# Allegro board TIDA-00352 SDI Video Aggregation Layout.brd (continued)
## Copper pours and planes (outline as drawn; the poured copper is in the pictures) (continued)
VDDRB_HS on L8_PWR: 77.6,177.16 77.6,116.08 37.08,116.08 37.08,74.93 42.55,74.93 42.55,79.25 48.01,79.25 48.01,108.2 86.23,108.2 86.23,177.16
VDDRB_LS on TOP (solid shape): 85.09,137.54 83.31,137.54 83.31,139.45 85.09,139.45
VDDRB_LS on L8_PWR: 86.87,160.02 86.87,107.57 48.51,107.57 48.51,74.68 64.64,74.68 64.64,97.54 94.36,97.54 94.36,160.02
VDDT on TOP (solid shape): 114.3,127 112.39,127 112.39,128.78 114.3,128.78
VDDT on L5_PWR: 29.97,50.17 29.97,73.32 30.03,73.41 30.14,73.39 30.88,73.7 30.14,74.01 30.03,73.99 29.97,74.08 29.97,91.8 30.46,92.67 29.97,93.54 29.97,94.59 30.01,94.6 30.45,95.2 30.01,95.81 29.97,95.82 29.97,96.52 108.46,96.52 108.46,99.34 108.49,99.41 108.56,99.44 109.02,99.87 108.56,100.3 108.49,100.33 108.46,100.41 108.46,106.4 108.49,106.47 108.56,106.5 109.02,106.93 108.56,107.37 108.49,107.39 108.46,107.47 108.46,117.43 108.47,117.6 108.46,117.77 108.46,117.78 108.46,129.41 118.14,129.41 118.49,129.23 118.84,129.41 126.36,129.41 126.36,88.65 99.44,88.65 99.44,81.41 99.31,81.41 99.31,71.5 47.75,71.5 47.75,76.33 42.93,76.33 42.93,73.79 43.43,73.79 43.43,72.64 42.93,72.64 42.93,50.17
1P0V_A1 on TOP (solid shape): 91.82,43.56 91.82,40.64 92.68,40.64 92.68,38.88 92.32,38.88 92.32,39.87 92.03,39.87 92.03,38.88 91.67,38.88 91.67,39.87 91.38,39.87 91.38,38.88 91.02,38.88 91.02,39.87 90.11,39.87 90.11,37.61 89.1,37.61 89.09,43.56
1P0V_A2 on TOP (solid shape): 111.63,124.71 111.63,121.79 112.49,121.79 112.49,120.03 112.14,120.03 112.14,121.02 111.84,121.02 111.84,120.03 111.49,120.03 111.49,121.02 111.19,121.02 111.19,120.03 110.84,120.03 110.84,121.02 109.93,121.02 109.93,118.76 108.91,118.76 108.9,124.72
1P0V_D1 on TOP (solid shape): 114.3,87.38 114.3,84.45 115.16,84.45 115.16,82.69 114.8,82.69 114.8,83.68 114.51,83.68 114.51,82.69 114.15,82.69 114.15,83.68 113.86,83.68 113.86,82.69 113.5,82.69 113.5,83.68 112.59,83.68 112.59,81.42 111.58,81.42 111.57,87.38
1P0V_D2 on TOP (solid shape): 112.27,43.81 112.27,40.89 113.13,40.89 113.13,39.13 112.77,39.13 112.77,40.12 112.48,40.12 112.48,39.13 112.12,39.13 112.12,40.12 111.83,40.12 111.83,39.13 111.47,39.13 111.47,40.12 110.56,40.12 110.56,37.86 109.55,37.86 109.54,43.82
1P5V on TOP (solid shape): 93.34,150.37 90.42,150.37 90.42,149.51 88.66,149.51 88.66,149.87 89.65,149.87 89.65,150.16 88.66,150.16 88.66,150.52 89.65,150.52 89.65,150.81 88.66,150.81 88.66,151.17 89.65,151.17 89.65,152.07 87.39,152.07 87.39,153.09 93.35,153.1
1P8V on TOP (solid shape): 74.29,150.37 71.37,150.37 71.37,149.51 69.61,149.51 69.61,149.87 70.6,149.87 70.6,150.16 69.61,150.16 69.61,150.52 70.6,150.52 70.6,150.81 69.61,150.81 69.61,151.17 70.6,151.17 70.6,152.07 68.34,152.07 68.34,153.09 74.3,153.1
3P3V on TOP (solid shape): 98.42,124.71 98.42,121.79 99.29,121.79 99.28,120.03 98.93,120.03 98.93,121.02 98.63,121.02 98.63,120.03 98.28,120.03 98.28,121.02 97.98,121.02 97.98,120.03 97.63,120.03 97.63,121.02 96.72,121.02 96.72,118.76 95.7,118.76 95.69,124.72
3P3V on BOTTOM (solid shape): 55.12,37.34 53.85,37.34 53.85,39.12 50.67,39.12 50.67,40.51 53.85,40.51 53.85,43.05 55.12,43.05
3P3V on L5_PWR: 0.64,0.64 0.64,177.16 14.22,177.16 14.22,137.16 55.24,137.16 55.24,129.41 107.82,129.41 107.82,97.16 29.34,97.16 29.34,49.4 126.36,49.4 126.36,0.64 ; 2 cut-outs
3P3V_CLK on TOP (solid shape): 57.28,171.7 55.88,171.7 55.88,174.12 57.28,174.12
3P3V_CLK on TOP (solid shape): 57.28,165.1 55.88,165.1 55.88,167.51 57.28,167.51
3P3V_CLK on TOP (solid shape): 57.28,137.29 55.88,137.29 55.88,139.7 57.28,139.7
3P3V_CLK on TOP (solid shape): 57.4,158.5 56.01,158.5 56.01,160.91 57.4,160.91
3P3V_CLK on TOP (solid shape): 57.4,151.64 56.01,151.64 56.01,154.05 57.4,154.05
3P3V_CLK on TOP (solid shape): 57.4,144.15 56.01,144.15 56.01,146.56 57.4,146.56
3P3V_CLK on TOP (solid shape): 57.66,130.18 56.26,130.18 56.26,132.59 57.66,132.59
3P3V_CLK on TOP (solid shape): 64.26,172.97 64.26,170.05 65.12,170.05 65.12,168.29 64.76,168.29 64.76,169.28 64.47,169.28 64.47,168.29 64.11,168.29 64.11,169.28 63.82,169.28 63.82,168.29 63.46,168.29 63.46,169.28 62.56,169.28 62.56,167.02 61.54,167.02 61.53,172.98
3P3V_CLK on BOTTOM (solid shape): 57.4,171.7 55.88,171.7 55.88,174.12 57.4,174.12
3P3V_CLK on BOTTOM (solid shape): 57.4,165.1 55.88,165.1 55.88,167.51 57.4,167.51
3P3V_CLK on BOTTOM (solid shape): 57.4,158.5 55.88,158.5 55.88,160.91 57.4,160.91
3P3V_CLK on BOTTOM (solid shape): 57.4,151.64 55.88,151.64 55.88,154.05 57.4,154.05
3P3V_CLK on BOTTOM (solid shape): 57.4,137.16 55.88,137.16 55.88,139.57 57.4,139.57
3P3V_CLK on BOTTOM (solid shape): 57.53,144.15 56.01,144.15 56.01,146.56 57.53,146.56
3P3V_CLK on BOTTOM (solid shape): 57.78,130.18 56.26,130.18 56.26,132.59 57.78,132.59
3P3V_CLK on L5_PWR: 55.75,177.16 55.75,129.92 126.36,129.92 126.36,177.16
3P3V_CLK on L12_PWR: 28.96,104.52 28.96,114.3 56.01,114.3 56.01,133.22 55.88,133.22 55.88,177.29 126.36,177.16 126.36,104.52
3P3V_RX on BOTTOM (solid shape): 59.69,38.23 59.44,38.23 59.44,36.96 58.93,36.96 58.93,37.34 56.9,37.34 56.9,40.01 59.69,40.01
3P3V_RX on L8_PWR: 48.77,0.64 48.77,21.72 36.07,21.72 36.07,34.29 41.53,34.29 41.53,26.8 46.23,26.8 46.23,34.29 53.98,34.29 53.98,40.01 61.72,40.01 61.72,43.69 126.36,43.69 126.36,0.64
3P3V_TX on BOTTOM (solid shape): 59.44,42.29 59.69,42.29 59.69,40.51 56.9,40.51 56.9,43.18 58.93,43.18 58.93,43.31 59.44,43.31
3P3V_TX on L8_PWR: 0.64,0.64 0.64,43.69 60.96,43.69 60.96,40.51 53.34,40.51 53.34,34.92 45.72,34.92 45.72,27.3 41.91,27.3 41.91,35.05 38.61,35.05 38.61,34.42 35.56,34.42 35.56,21.21 48.26,21.21 48.26,0.64
CLK_DVDD on BOTTOM (solid shape): 55.5,130.18 54.1,130.18 54.1,132.59 55.5,132.59
CLK_DVDD on L12_PWR: 55.5,132.59 42.42,132.59 42.42,122.05 11.43,122.05 11.43,146.3 19.3,146.3 19.3,177.16 0.64,177.16 0.64,104.52 28.45,104.52 28.45,114.94 55.5,114.94
CLK_VCC on BOTTOM (solid shape): 55.24,144.15 53.85,144.15 53.85,146.56 55.24,146.56
CLK_VCC on L12_PWR: 55.37,140.97 32.64,140.97 32.64,130.05 19.81,130.05 19.81,177.16 55.37,177.16
CLK_VDD_IN on BOTTOM (solid shape): 55.12,137.16 53.72,137.16 53.72,139.57 55.12,139.57
CLK_VDD_IN on L12_PWR: 55.37,140.34 33.27,140.34 33.27,129.41 19.3,129.41 19.3,145.8 12.06,145.8 12.06,122.68 41.78,122.68 41.78,133.22 55.37,133.22
CLK_VDD_OUTA on BOTTOM (solid shape): 55.12,151.64 53.72,151.64 53.72,154.05 55.12,154.05
CLK_VDD_OUTA on L5_PWR: 55.24,155.07 31.88,155.07 31.88,142.37 20.07,142.37 20.07,137.67 55.24,137.67
CLK_VDD_OUTB on BOTTOM (solid shape): 55.12,158.5 53.72,158.5 53.72,160.91 55.12,160.91
CLK_VDD_OUTB on L5_PWR: 55.24,164.08 27.05,164.08 27.05,146.3 14.86,146.3 14.86,137.67 19.43,137.67 19.43,142.88 31.24,142.88 31.24,155.7 55.24,155.7
CLK_VDD_PLL on BOTTOM (solid shape): 55.12,165.1 53.72,165.1 53.72,167.51 55.12,167.51
CLK_VDD_PLL on L5_PWR: 55.24,170.43 22.23,170.43 22.23,146.81 26.54,146.81 26.54,164.72 55.24,164.72
CLK_VDD_PLL_A on BOTTOM (solid shape): 55.12,171.7 53.72,171.7 53.72,174.12 55.12,174.12
CLK_VDD_PLL_A on L5_PWR: 55.24,171.07 21.59,171.07 21.59,146.81 14.86,146.81 14.86,177.16 55.24,177.16
Net_257 on TOP (solid shape): 100.25,149.44 100.42,149.32 100.54,149.14 100.58,148.94 100.52,148.7 100.42,148.54 100.23,148.41 100.03,148.38 99.81,148.42 99.64,148.53 99.51,148.72 99.47,148.93 99.51,149.16 99.62,149.31 99.82,149.45 100.03,149.48
Net_258 on TOP (solid shape): 97.92,151.04 97.92,149.15 98.06,148.46 98.28,148.14 98.64,147.98 99.22,148 99.08,146.99 98.56,146.99 98.43,146.14 98.95,146.14 98.69,144.27 98.69,144.11 98.77,143.93 98.96,143.69 99.1,143.59 99.33,143.49 99.61,143.41 100.04,143.37 100.39,143.41 100.54,143.48 100.57,143.55 100.58,144.07 100.41,144.09 100.21,144.13 100.14,144.19 100.1,144.31 100.37,146.14 100.91,146.14 101.06,146.98 100.53,147 100.71,148.07 100.94,148.15 101.6,148.2 102.3,148.08 102.66,147.84 103.23,147.74 103.21,146.56 103.38,146.14 103.51,145.56 103.58,144.64 103.51,143.58 103.42,143.27 103.28,143.11 103,142.99 102.21,142.79 101.63,142.51 100.48,142.07 99.77,141.52 99.23,140.88 98.99,140.1 99.03,139.56 99.12,139.15 99.31,138.56 99.31,138.39 98.88,138.49 98.41,138.54 98,138.84 97.8,138.91 97.59,139.27 96.81,140.89 96.49,141.52 96.03,142.63 95.68,143.12 95.43,143.26 95.07,143.25 94.64,143.01 94.49,142.88 94.18,142.81 93.96,142.87 93.69,143.17 93.28,143.65 92.95,144.18 92.56,144.64 92.15,145.06 91.66,145.25 91.47,145.42 91.4,145.6 91.29,145.78 95.07,145.78 95.07,151.05
Net_259 on TOP (solid shape): 99.92,144.56 98.95,144.55 99.43,147.85 100.4,147.86

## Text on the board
BOTTOM: LAYER16-BOTTOM(TESTER)SIDE
Package Geometry/Pastemask Bottom: SPB
Ref Des/Silkscreen Bottom: SBW
User.Comments: MB | MT
TOP: TLK10xxxEVM | MOTHER BOARD | 6566789 | REV B | J | N | LAYER1-TOP-DUT SIDE
Board Geometry/Soldermask Top: TLK10xxxEVM | MOTHER BOARD | 6566789 | REV B | J | N
Package Geometry/Pastemask Top: SPT
Ref Des/Silkscreen Top: HIGH | LOW | 2p5V | MDIOV | GND | 3P3V_CLK | ST/GPI1 | SIGNAL* | RCLK_SEL | MODE_SEL | PDTRXB | GPI1 | ST | TESTEN | 232 | H10 | M9 | MDIO_B2B_RLY | MDIO_CON_RLY | PRBSEN | 022 | 081 | REF_SEL | SI_MODE0 | SI_MODE1 | 3P3V | 1P8V | 1P5V | PDTRXA | 1P0V_D2 | 1P0V_D1 | M9 * | 1P0V_A2 | H10 * | MODE/REFCLK_SEL | 1P0V_A1 | GPIO | B2B_RLY | CON_RLY | I2C_ADDR | I2C_GPIO_ADDR | STATUS1/PIN0 | SPI_LE2 | SPI_CLK/PIN4 | SPI_LE1/PIN3 | SPI_MISO/PIN2 | SPI_MOSI/PIN1 | DIS | EN | PRI_REF | SEC_REF | (30.72MHZ) | (31.25MHZ) | CLK BUFFER INPUT | CLKA | (STATUS0) | CLKB | PLL_LOCK | RST/PWR | 3p3V | SYNCN | PDN | RST | BTN | PRI_REF_IN_N | STATUS1 | PRI_OSC | SEC_OSC | CLK | EXT | GEN | SMA | RESET | MDC | OUTPUT | MDIO | INPUT | I2C | JTAG | MOD_DEF2_SDA | MOD_DEF1_SCL | MOD DETECT | SFP+ | TX_DIS | JTAG_V | PRTAD0 | 12C_LS_EN | REGULATOR | DISABLE | 23 | 22 | 1p0V_D1 | 5V | REG | PRI_REF_IN_P | INT2 | RESET2 | INT1 | RESET1 | SDA | SCL | TX_FAULT | TX DIS | TCK | TMS | RX_LOS | TDI | TDO | TRST | LS_OK | OUT_B | PRTAD4 | PRTAD3 | OUT_A | PRTAD2 | PRTAD1 | PRBS | PASS | LOSB | IN | OUT | LOSA | LS_OKINB | LS_OKINA | AMUXB | AMUXA | HSTXBn | HSTXBp | HSRXBp | HSRXBn | USB DONGLE | CLKOUTBn | REFCLK0n | CLKOUTBp | REF | CLK0p | RST/ | PWR | CLKOUTAn | CLK1n | REFCLK1p | CLKOUTAp | 1p8V | 3p3V_CLK | 1p5V | VOLTAGE MONITOR DONGLE | 1p5/8V | MAIN | STW | PLUG | 1p0V_A1 | BJ | 1p0V_D2 | 1p0V_A2 | +5V
L2_GND: LAYER2-GND
L3_SIG2: LAYER3-SIGNAL
L4_GND: LAYER4-GND
L5_PWR: LAYER5-PWR
L6_GND: LAYER6-GND
L7_GND: LAYER7-GND
L8_PWR: LAYER8-PWR
L9_GND: LAYER9-GND
L10_PWR: LAYER10-PWR
L11_GND: LAYER11-GND
L12_PWR: LAYER12-PWR
L13_GND: LAYER13-GND
L14_SIG3: LAYER14-SIGNAL
L15_GND: LAYER15-GND
PAGE_OUTLINE: J. NERGER | LT/DFW TEST | 04/16/13 | 6566789 | A | TLK10xxx EVM MOTHER BOARD | Texas Instruments Inc. | 12500 TI Boulevard | Dallas, TX 75243 | WO# 73776
COMPVAL_TYPE_TOP: FR-4 | Pre-preg 0.010" | Core 0.005" | 1.0oz / 1.0oz Layer 8 & 9 | (material) | LAYER 8 | LAYER 9
COMPVAL_TYPE_BOTTOM: ASSEMBLY | 1 | / | 2
USER_PART_NUM_TOP: ASSEMBLY | 2 | /
User.8: FABRICATION | 1 | / | GENERAL NOTES. UNLESS OTHERWISE SPECIFIED | 1.  ALL FABRICATION ITEMS MUST MEET OR EXCEED BEST | INDUSTRY PRACTICE : IPC-A-600C (Commercial std.) | 2.  LAMINATE MATERIAL  :  ROGERS 4350B or EQUIVALENT BETWEEN | LAYERS 1 & 2 AND LAYERS 15 &16 | FR4 POLYCLAD OR EQUIVALENT FOR ALL OTHER LAYERS | 3.  COPPER WEIGHT  : 1oz START INTERNAL, 1/2oz START EXTERNAL | 4.  FINISHED BOARD THICKNESS :  .111 +/-10% | 5.  MAXIMUM WARP AND TWIST TO BE :  .005 INCH PER INCH | 6.  MINIMUM COPPER WALL THICKNESS OF PLATED-THRU | HOLES TO BE .001 INCH. THERE MUST BE 1MIL OR GREATER PLATING ON | EACH SIDE OF THE BARREL WHEN VIEWED IN THE CROSS SECTION | 7.  MINIMUM ANNULAR RING OF PLATED-THRU HOLES | TO BE .002 INCH | 8.  MINIMUM ALLOWABLE LINE REDUCTION TO BE | 20% OR .002 WHICHEVER IS GREATER | 9.  0.010 SIGNAL LINES ON LAYERS 1 & 16 TO BE | IMPEDANCE CONTROLLED 50 OHMS +/- 10% | 10. 0.006 SIGNAL LINES ON LAYER 3 & 14 TO BE | 11.0.004.5 SIGNAL LINES ON LAYER 1,3, & 16 TO BE | IMPEDANCE CONTROLLED 100 OHMS +/- 10% | 12. DIELECTRIC CONSTANTS ARE | ROGERS 4350: 3.6 | FR4 POLYCLAD: 4.1 | 13. VIA'S IN SMT DEVICE PADS TO BE FILLED WITH NON-CONDUCTIVE EPOXY. | ANY VOID IN THE FILL MATERIAL MUST NOT BE GREATER THAN 25% | OF THE FINISHED HOLE DIAMETER.  SEE DRILL NOTE #1 | 14. A CROSS SECTION MOUNT AND DIGITAL PHOTO'S OF VIA'S TO BE PROVIDED | 15. USE THE (DRPP) DUTCH REVERSE PLATING PROCESS | PROCESS NOTES | 1. CIRCUITRY ON OUTER LAYERS TO BE PLATED WITH : NICKEL GOLD | 2. SOLDERMASK BOTH SIDES PER ARTWORK  :  BLUE LPI | 3. SILKSCREEN BOTH SIDES PER ARTWORK  :  COLOR = WHITE | DRILL NOTES | 1. 0.0081" DRILL SHOULD NOT BE EXPOY FILLED. | 2. 0.0081" DRILL IS A REFERENCE NAME, ALL 0.0081" DRILLS SHOULD BE | DRILLED TO 0.008".
User.16: FIGURE | SIZE | 6.0 | 8.0 | 12.2 | 24.0 | 33.46 | 37.4 | 38.0 | 41.34 | 44.0 | 50.0 | 82.68 | 120.0 | 140.0 | 250.0 | 47.01 | 61.02 | 130.0 | DRILL CHART: TOP to BOTTOM | ALL UNITS ARE IN MILS | TOLERANCE | +0.0/-0.0 | +0.0/-8.0 | +3.0/-12.0 | +3.0/-3.0 | +2.0/-2.0 | PLATED | NON-PLATED | QTY | 129 | 15 | 2085 | 64 | 50 | 1 | 9 | 36 | 10 | 40 | 16 | 8 | 2 | 4 | 12
